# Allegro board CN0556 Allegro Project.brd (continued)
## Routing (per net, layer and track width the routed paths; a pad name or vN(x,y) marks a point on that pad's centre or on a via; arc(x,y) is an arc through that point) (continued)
V1_ADC: length 143.4
  TOP w0.305: U4.4 46.76,34.42 47.24,33.93 47.24,33.2 47.92,32.52 U4.1 v1(48.62,31.62)
  L3_PWR w0.305: v1(48.62,31.62) 49.76,32.77 58.37,32.77 67.23,23.9 119.38,23.9 124.31,28.83 175.97,28.83 ADCCON.19
V1D: length 121.6
  TOP w0.203: U1.36 92.31,54.62 91.87,54.18
  TOP w0.508: 91.87,54.18 89.46,54.18 88.95,54.69 C2.1 v1(86.74,55.68) ; R1.2 83.24,44.53 82.26,43.55 RFB1A.1 82.21,43.23 C1.1 82.21,37.86 v1(82.19,37.85)
  L3_PWR w0.508: v1(38.94,81.91) 38.94,42.16 43.13,37.97 82.07,37.97 v1(82.19,37.85) 84.68,37.85 86.74,39.9 v1(86.74,55.68)
  vias: v1(40.06,88.98) v1(40.31,87.2) v1(40.31,86.31) v1(40.31,85.29) v1(40.31,84.4) v1(40.31,83.52) v1(40.31,82.63) v1(40.44,101.3) v1(40.46,99.39) v1(40.46,96.9) v1(40.44,95.55) v1(40.44,94.28) v1(40.41,93.07) v1(40.39,91.72) v1(40.39,90.4) v1(40.44,88.21) v1(40.56,108.53) v1(40.56,107.77) v1(40.56,106.88) v1(40.56,105.99) v1(40.56,104.98) v1(40.56,104.09) v1(40.56,103.2) v1(40.56,102.31) v1(40.49,98.12) v1(40.82,100.53) v1(40.94,88.98) v1(41.07,96.24) v1(41.05,93.75) v1(41.02,92.41) v1(41,91.01) v1(41.17,98.73) v1(41.1,97.59) v1(41.12,94.89) v1(41.33,108.53) v1(41.33,101.3) v1(41.33,88.21) v1(41.55,106.4) v1(41.55,105.51) v1(41.55,104.62) v1(41.55,103.73) v1(41.55,102.84) v1(41.5,86.61) v1(41.5,85.72) v1(41.5,84.84) v1(41.5,83.95) v1(41.5,83.06) v1(41.66,91.72) v1(41.58,90.32) v1(41.71,100.53) v1(41.73,99.42) v1(41.76,98.12) v1(41.73,96.9) v1(41.71,95.55) v1(41.71,94.28) v1(41.68,93.07) v1(41.83,88.98) v1(42.09,108.53) v1(42.21,101.3) v1(42.27,91.01) v1(42.21,88.21) v1(42.27,87) v1(42.27,86.11) v1(42.27,85.22) v1(42.27,84.33) v1(42.27,83.44) v1(42.32,106.78) v1(42.32,105.89) v1(42.32,105) v1(42.32,104.11) v1(42.32,103.23) v1(42.37,97.56) v1(42.34,96.22) v1(42.34,94.89) v1(42.32,93.73) v1(42.29,92.38) v1(42.39,98.73) v1(42.6,100.53) v1(42.72,88.98) v1(42.85,108.53) v1(42.88,91.72) v1(42.85,90.32) v1(42.98,98.12) v1(42.95,96.9) v1(42.93,95.55) v1(42.93,94.28) v1(42.9,93.07) v1(43,99.42) v1(43.1,101.3) v1(43.1,88.21) v1(43.36,87.2) v1(43.36,86.31) v1(43.36,85.29) v1(43.36,84.4) v1(43.36,83.52) v1(43.36,82.63) v1(43.48,100.53) v1(43.56,96.22) v1(43.56,94.95) v1(43.54,93.73) v1(43.51,92.38) v1(43.48,91.01) v1(43.61,108.53) v1(43.61,107.77) v1(43.61,106.88) v1(43.61,105.99) v1(43.61,104.98) v1(43.61,104.09) v1(43.61,103.2) v1(43.61,102.31) v1(43.61,98.78) v1(43.59,97.56) v1(43.61,88.98) v1(43.99,101.3) v1(44.07,93.09) v1(44.04,91.74) v1(43.99,88.21) v1(44.17,98.15) v1(44.15,96.93) v1(44.12,95.58) v1(44.09,94.31) v1(44.37,100.53) v1(44.5,88.98) v1(44.68,92.43) v1(44.65,91.03) v1(44.75,96.27) v1(44.7,93.78) v1(44.86,98.76) v1(44.78,97.61) v1(44.78,94.92) v1(44.88,101.3) v1(44.88,88.21) v1(45.26,100.53) v1(45.36,94.31) v1(45.34,93.09) v1(45.31,91.74) v1(45.44,98.15) v1(45.42,96.93) v1(45.39,95.58) v1(45.39,88.98) v1(45.77,101.3) v1(45.77,88.21) v1(45.97,93.75) v1(45.95,92.41) v1(45.92,91.03) v1(46.08,98.76) v1(46.05,97.59) v1(46.02,96.24) v1(46,94.92) v1(46.15,100.53) v1(46.28,88.98) v1(46.56,93.09) v1(46.53,91.74) v1(46.66,101.3) v1(46.66,98.15) v1(46.63,96.93) v1(46.61,95.58) v1(46.58,94.31) v1(46.66,88.21) v1(47.04,100.53) v1(47.17,92.41) v1(47.14,91.03) v1(47.17,88.98) v1(47.27,97.59) v1(47.24,96.24) v1(47.22,94.97) v1(47.19,93.75) v1(47.29,98.81) v1(47.55,101.3) v1(47.55,88.21) v1(47.93,100.53) v1(47.93,88.98) v1(48.31,101.3) v1(48.31,88.21) v1(48.69,100.53) v1(50.01,82.98) v1(50.09,85.55) v1(50.32,107.29) v1(50.47,84.79) v1(50.39,82.22) v1(50.6,105.11) v1(50.7,106.53) v1(50.98,104.34) v1(50.98,85.55) v1(50.9,82.98) v1(51.21,107.29) v1(51.36,84.79) v1(51.28,82.22) v1(51.49,105.11) v1(51.59,106.53) v1(51.87,104.34) v1(51.87,85.55) v1(51.79,82.98) v1(52.1,107.29) v1(52.17,82.22) v1(52.25,84.79) v1(52.37,105.11) v1(52.48,106.53) v1(52.76,104.34) v1(52.76,85.55) v1(52.68,82.98) v1(52.98,107.29) v1(53.06,82.22) v1(53.14,84.79) v1(53.26,105.11) v1(53.37,106.53) v1(53.57,82.98) v1(53.64,104.34) v1(53.64,85.55) v1(53.87,107.29) v1(53.95,82.22) v1(54.03,84.79) v1(54.15,105.11) v1(54.25,106.53) v1(54.53,104.34) v1(54.53,85.55) v1(54.91,84.79) v1(55.04,105.11) v1(55.42,104.34) v1(55.42,85.55) v1(55.8,84.79) v1(55.93,105.11) v1(56.16,96.44) v1(56.16,95) v1(56.13,93.57) v1(56.18,97.92) v1(56.31,104.34) v1(56.31,85.55) v1(56.39,82.93) v1(56.57,107.31) v1(56.57,97.16) v1(56.54,95.68) v1(56.54,94.23) v1(56.52,92.81) v1(56.69,84.79) v1(56.77,82.17) v1(56.82,105.11) v1(56.95,106.55) v1(57.07,97.92) v1(57.05,96.44) v1(57.05,95) v1(57.02,93.57) v1(57.2,104.34) v1(57.2,85.55) v1(57.28,82.93) v1(57.45,107.31) v1(57.45,97.16) v1(57.43,95.68) v1(57.43,94.23) v1(57.4,92.81) v1(57.58,84.79) v1(57.66,82.17) v1(57.71,105.11) v1(57.84,106.55) v1(57.96,97.92) v1(57.94,96.44) v1(57.94,95) v1(57.91,93.57) v1(57.96,85.55) v1(58.09,104.34) v1(58.17,82.93) v1(58.34,107.31) v1(58.34,97.16) v1(58.32,95.68) v1(58.32,94.23) v1(58.29,92.81) v1(58.34,84.79) v1(58.47,105.11) v1(58.55,82.17) v1(58.72,106.55) v1(58.85,104.34) v1(58.85,97.92) v1(58.83,96.44) v1(58.83,95) v1(58.8,93.57) v1(59.05,82.93) v1(59.23,107.31) v1(59.23,97.16) v1(59.21,95.68) v1(59.21,94.23) v1(59.18,92.81) v1(59.44,82.17) v1(59.61,106.55) v1(59.74,97.92) v1(59.72,96.44) v1(59.72,95) v1(59.69,93.57) v1(59.94,82.93) v1(60.07,92.81) v1(60.12,107.31) v1(60.12,97.16) v1(60.1,95.68) v1(60.1,94.23) v1(60.33,82.17) v1(60.5,106.55)
V2_ADC: length 131.2
  TOP w0.305: U5.4 56.54,34.42 57.15,33.81 57.15,32.87 57.51,32.52 U5.1 v1(58.4,31.62)
  L3_PWR w0.305: v1(58.4,31.62) 66.73,23.29 119.89,23.29 122.89,26.29 178.51,26.29 ADCCON.23
V2D: length 106.9
  TOP w0.508: R14.1 103.49,42.71 103.44,42.76 ; 103.44,42.76 C6.1 104.68,41.01 v1(104.69,41.02) ; 103.44,42.76 RFB2A.1
  L3_PWR w0.508: v1(104.69,41.02) 106.67,39.04 160.6,39.04 167.72,46.15 v1(167.72,81.91)
  vias: v1(166.52,109.17) v1(166.52,106.63) v1(166.52,104.09) v1(166.52,101.55) v1(166.52,88.85) v1(166.52,86.31) v1(166.52,83.77) v1(166.52,81.23) v1(167.11,98.68) v1(167.13,97.46) v1(167.16,96.11) v1(167.11,94.79) v1(167.18,93.72) v1(167.59,107.95) v1(167.59,105.41) v1(167.59,102.87) v1(167.59,100.33) v1(167.59,90.17) v1(167.59,87.63) v1(167.59,85.09) v1(167.59,82.68) v1(167.72,98.12) v1(167.74,96.77) v1(167.72,95.5) v1(167.84,109.22) v1(167.79,94.18) v1(168.33,98.68) v1(168.35,97.46) v1(168.38,96.11) v1(168.38,94.79) v1(168.45,93.72) v1(168.86,106.68) v1(168.86,104.14) v1(168.86,101.6) v1(168.86,88.9) v1(168.86,86.36) v1(168.86,83.82) v1(168.86,81.91) v1(168.99,109.22) v1(168.99,98.15) v1(169.01,96.8) v1(169.04,95.5) v1(169.06,94.18) v1(170,81.91) v1(170.13,109.22) v1(170.13,107.95) v1(170.13,105.41) v1(170.13,102.87) v1(170.13,100.33) v1(170.13,90.17) v1(170.13,87.63) v1(170.13,85.09) v1(170.13,82.68) v1(170.23,98.15) v1(170.26,96.8) v1(170.28,95.5) v1(170.33,94.18) v1(170.87,98.68) v1(170.89,97.46) v1(170.92,96.11) v1(170.92,94.79) v1(170.92,93.5) v1(170.92,92.08) v1(171.27,81.91) v1(171.4,109.22) v1(171.4,106.68) v1(171.4,104.14) v1(171.4,101.6) v1(171.45,92.78) v1(171.4,91.44) v1(171.4,88.9) v1(171.4,86.36) v1(171.4,83.82) v1(171.5,99.92) v1(171.5,98.02) v1(171.53,96.8) v1(171.55,95.45) v1(171.5,94.13) v1(172.06,92.1) v1(172.09,98.63) v1(172.11,97.46) v1(172.14,96.11) v1(172.11,94.84) v1(172.11,93.45) v1(172.42,81.91) v1(172.54,109.22) v1(172.67,107.95) v1(172.67,105.41) v1(172.67,102.87) v1(172.67,100.33) v1(172.67,90.17) v1(172.67,87.63) v1(172.67,85.09) v1(172.67,82.68) v1(172.72,98.02) v1(172.75,96.8) v1(172.77,95.45) v1(172.77,94.13) v1(172.72,92.78) v1(173.28,92.1) v1(173.3,98.63) v1(173.33,93.45) v1(173.38,97.49) v1(173.41,96.14) v1(173.43,94.84) v1(173.56,81.91) v1(173.69,109.22) v1(173.94,106.68) v1(173.94,104.14) v1(173.94,101.6) v1(173.94,91.44) v1(173.94,88.9) v1(173.94,86.36) v1(173.94,83.82) v1(173.99,98.02) v1(174.02,96.8) v1(174.04,95.45) v1(174.04,94.13) v1(173.99,92.78) v1(174.09,99.72) v1(174.83,81.91) v1(174.96,109.22) v1(175.21,107.95) v1(175.21,105.41) v1(175.21,102.87) v1(175.21,100.33) v1(175.21,97.79) v1(175.21,95.25) v1(175.21,92.71) v1(175.21,90.17) v1(175.21,87.63) v1(175.21,85.09) v1(175.21,82.68) v1(175.97,81.91) v1(176.1,109.22) v1(176.35,99.06) v1(176.35,96.52) v1(176.35,93.98) v1(176.35,91.44) v1(176.48,88.9) v1(176.48,86.36) v1(176.48,83.82) v1(177.11,81.91) v1(177.24,109.22) v1(177.75,107.95) v1(177.75,105.41) v1(177.75,102.87) v1(177.75,100.33) v1(177.75,97.79) v1(177.75,95.25) v1(177.75,92.71) v1(177.75,89.79) v1(177.75,87.63) v1(177.75,85.09) v1(177.75,82.68) v1(178.51,109.22) v1(178.51,81.91) v1(179.02,106.68) v1(179.02,104.14) v1(179.02,101.6) v1(179.02,99.06) v1(179.02,96.52) v1(179.02,93.98) v1(179.02,91.44) v1(179.02,88.9) v1(179.02,86.36) v1(179.02,83.82) v1(179.65,109.22) v1(179.65,81.91) v1(180.29,107.95) v1(180.29,105.41) v1(180.29,102.87) v1(180.29,100.33) v1(180.29,97.79) v1(180.29,95.25) v1(180.29,92.71) v1(180.29,90.17) v1(180.29,87.63) v1(180.29,85.09) v1(180.42,82.68) v1(180.8,109.22) v1(180.8,81.91) v1(181.56,106.68) v1(181.56,104.14) v1(181.56,101.6) v1(181.56,99.06) v1(181.56,96.52) v1(181.56,93.98) v1(181.56,91.44) v1(181.56,88.9) v1(181.56,86.36) v1(181.56,83.82) v1(182.7,82.55) v1(182.83,105.41) v1(182.83,102.87) v1(182.83,100.33) v1(182.83,97.79) v1(182.83,95.25) v1(182.83,92.71) v1(182.83,87.63) v1(182.83,85.09) v1(182.96,89.79) v1(183.72,110.11) v1(183.72,108.97) v1(183.72,107.82) v1(183.72,83.19) v1(183.72,82.04) v1(183.72,80.9) v1(184.1,106.68) v1(184.1,104.14) v1(184.1,101.6) v1(184.1,99.06) v1(184.1,96.52) v1(184.1,93.98) v1(184.1,91.44) v1(184.1,88.9) v1(184.1,86.36) v1(185.37,89.28) v1(185.37,87.63) v1(185.37,85.09) v1(185.5,105.41) v1(185.5,102.87) v1(185.5,100.33) v1(185.5,97.79) v1(185.5,95.25) v1(185.5,93.34)
BG:
  vias: v1(73.61,116.08) v1(73.61,115.32) v1(74.37,116.08) v1(74.37,115.32) v1(79.83,75.31) v1(79.81,74.55) v1(80.59,75.31) v1(80.59,74.55) v1(85.67,116.08) v1(85.67,115.32) v1(86.51,116.08) v1(86.51,115.32) v1(91.9,75.31) v1(91.9,74.55) v1(92.66,75.31) v1(92.66,74.55) v1(99.64,75.31) v1(99.64,74.55) v1(100.41,75.31) v1(100.41,74.55) v1(105.61,64.9) v1(105.61,64.13) v1(106.38,64.9) v1(106.38,64.13)
BIAS: length 45.9
  TOP w0.305: U1.29 95.81,57.73 v1(96.01,57.94) ; R9.1 59.59,42.93 v1(76.63,42.93)
  BOTTOM w0.305: v1(76.63,42.93) 82.12,42.93 96.01,56.82 v1(96.01,57.94)
BOOSTOUT: length 172.9
  TOP w0.508: R2.2 80.72,44.31 v1(80.72,35.31) ; D3.A 97.84,65.31 v1(97.84,66.07) ; R1B.1 v1(52.03,35.51)
  L3_PWR w0.508: v1(97.84,66.07) 97.84,60.93 96.85,59.94 92.51,59.94 90.22,57.66 90.22,50.24 91.69,48.77 91.69,45.16 92.59,44.27 92.59,36.1 91.8,35.31 v1(80.72,35.31) 80.52,35.51 v1(52.03,35.51) 25.53,35.51 20.52,40.51 20.52,88.27 v1(19.71,89.08)
  vias: v1(3.15,93.78) v1(3.15,92.76) v1(3.15,91.74) v1(3.89,94.23) v1(3.89,93.22) v1(3.89,92.2) v1(3.89,91.19) v1(4.5,93.68) v1(5.03,94.36) v1(5.08,92.25) v1(5.46,91.49) v1(5.51,93.68) v1(5.97,92.25) v1(6.05,94.36) v1(6.35,91.49) v1(6.53,93.68) v1(6.86,92.25) v1(7.06,94.36) v1(7.24,91.49) v1(7.54,93.68) v1(7.75,92.25) v1(8.08,94.36) v1(8.13,91.49) v1(8.56,93.68) v1(8.59,109.22) v1(8.64,92.25) v1(8.77,110.6) v1(8.77,107.84) v1(9.02,91.49) v1(9.09,94.36) v1(9.3,111.89) v1(9.3,106.55) v1(9.58,93.68) v1(10.15,112.99) v1(10.15,105.45) v1(10.11,94.36) v1(10.59,93.68) v1(10.59,92.66) v1(10.59,91.64) v1(10.59,90.63) v1(11.25,113.84) v1(11.25,104.6) v1(11.25,94.36) v1(11.35,93.04) v1(11.35,92.02) v1(11.35,91.01) v1(12.54,114.37) v1(12.54,104.07) v1(13.92,114.55) v1(13.92,103.89) v1(15.3,114.37) v1(15.3,104.07) v1(16.59,113.84) v1(16.59,104.6) v1(17.69,112.99) v1(17.69,105.45) v1(18.47,99.77) v1(18.47,98.76) v1(18.47,97.74) v1(18.47,96.72) v1(18.47,95.71) v1(18.47,94.69) v1(18.47,93.68) v1(18.47,92.66) v1(18.47,91.64) v1(18.47,90.63) v1(18.47,89.61) v1(18.54,111.89) v1(18.54,106.55) v1(19.07,110.6) v1(19.07,107.84) v1(19.25,109.22) v1(19.23,99.26) v1(19.23,98.25) v1(19.23,97.23) v1(19.23,96.22) v1(19.23,95.2) v1(19.23,94.18) v1(19.23,93.17) v1(19.23,92.15) v1(19.23,91.14) v1(19.23,90.12) v1(19.74,100.03) v1(20.24,99.39) v1(20.75,100.03) v1(20.7,97.74) v1(20.73,96.52) v1(20.75,95.17) v1(20.78,93.9) v1(20.8,92.68) v1(20.83,91.34) v1(20.85,89.97) v1(21.26,99.39) v1(21.34,97.08) v1(21.36,95.86) v1(21.39,94.51) v1(21.41,93.24) v1(21.44,92.02) v1(21.46,90.68) v1(21.77,100.03) v1(21.92,97.69) v1(21.95,96.52) v1(21.97,95.17) v1(22,93.85) v1(22.02,92.68) v1(22.05,91.34) v1(22.07,89.97) v1(22.28,99.39) v1(22.56,97.08) v1(22.58,95.86) v1(22.61,94.51) v1(22.63,93.24) v1(22.66,92.02) v1(22.68,90.68) v1(22.78,100.03) v1(23.14,97.69) v1(23.22,96.55) v1(23.24,95.2) v1(23.22,93.85) v1(23.29,99.39) v1(23.29,92.71) v1(23.32,91.36) v1(23.34,89.97) v1(23.8,100.03) v1(23.83,97.08) v1(23.85,95.86) v1(23.88,94.51) v1(23.9,93.24) v1(23.93,92.02) v1(23.95,90.68) v1(24.31,99.39) v1(24.38,97.71) v1(24.41,96.49) v1(24.43,95.15) v1(24.43,93.88) v1(24.46,92.66) v1(24.49,91.31) v1(24.51,89.94) v1(24.82,100.03) v1(24.99,98.35) v1(25.02,97.05) v1(25.04,95.83) v1(25.07,94.49) v1(25.07,93.22) v1(25.1,92) v1(25.12,90.65) v1(25.15,89.26) v1(25.32,99.39) v1(25.6,97.66) v1(25.63,96.49) v1(25.65,95.15) v1(25.65,93.83) v1(25.68,92.66) v1(25.7,91.31) v1(25.73,89.94) v1(25.83,100.03) v1(26.26,98.35) v1(26.24,97.05) v1(26.26,95.83) v1(26.34,99.39) v1(26.29,94.49) v1(26.29,93.22) v1(26.31,92) v1(26.34,90.65) v1(26.42,89.26) v1(26.85,100.03) v1(26.82,97.66) v1(26.87,93.83) v1(26.9,96.52) v1(26.92,95.17) v1(26.95,92.68) v1(26.97,91.34) v1(27,89.94) v1(27.36,99.39) v1(27.53,98.32) v1(27.51,97.05) v1(27.53,95.83) v1(27.56,94.49) v1(27.56,93.22) v1(27.58,92) v1(27.61,90.65) v1(27.61,89.33) v1(27.86,100.03) v1(28.37,99.39)
BUCKOUT: length 240.3
  TOP w0.508: R13.1 106.25,42.65 v1(106.25,34.42) ; D2.A v1(102.54,66.01) ; R2B.1 v1(62.69,34.42)
  L3_PWR w0.508: 93.55,34.42 v1(106.25,34.42) 122.99,34.42 123.44,33.96 187.25,33.96 193.65,40.36 193.65,67.92 205.16,79.43 v1(205.16,90.63) ; 93.55,34.42 93.55,48.72 91.82,50.44 91.66,50.44 91.66,57.04 93.27,58.65 100.43,58.65 102.54,60.76 v1(102.54,66.01) ; 93.55,34.42 v1(62.69,34.42)
  vias: v1(204.19,109.14) v1(204.37,110.52) v1(204.37,107.76) v1(204.91,111.81) v1(204.91,106.47) v1(205.16,101.93) v1(205.16,100.91) v1(205.16,99.9) v1(205.16,98.88) v1(205.16,97.87) v1(205.16,96.85) v1(205.16,95.96) v1(205.16,95.07) v1(205.16,94.18) v1(205.16,93.29) v1(205.16,92.41) v1(205.16,91.64) v1(205.75,112.91) v1(205.75,105.37) v1(206.17,101.93) v1(206.17,100.91) v1(206.17,99.9) v1(206.17,98.88) v1(206.17,97.87) v1(206.17,96.85) v1(206.17,95.96) v1(206.17,95.07) v1(206.17,94.18) v1(206.17,93.29) v1(206.17,92.41) v1(206.17,91.64) v1(206.17,90.63) v1(206.86,113.76) v1(206.86,104.52) v1(207.19,101.93) v1(207.19,100.91) v1(207.19,99.9) v1(207.19,98.88) v1(207.19,97.87) v1(207.19,96.85) v1(207.19,95.96) v1(207.19,95.07) v1(207.19,94.18) v1(207.19,93.29) v1(207.34,91.16) v1(207.85,91.92) v1(208.14,114.29) v1(208.14,103.99) v1(208.36,91.16) v1(208.86,91.92) v1(209.37,91.16) v1(209.52,114.47) v1(209.52,103.81) v1(209.88,91.92) v1(210.39,91.16) v1(210.91,114.29) v1(210.91,103.99) v1(210.9,91.92) v1(211.4,91.16) v1(211.91,91.92) v1(212.17,90.65) v1(212.17,89.64) v1(212.17,88.62) v1(212.19,113.76) v1(212.19,104.52) v1(212.8,91.16) v1(212.8,90.14) v1(212.8,89.13) v1(213.3,112.91) v1(213.3,105.37) v1(214.14,111.81) v1(214.14,106.47) v1(214.68,110.52) v1(214.68,107.76) v1(214.86,109.14)
DG1: length 138.9
  TOP w0.508: v1(87.78,58.95) 87.76,58.93 87.1,58.93 86.45,58.28 R3.1
  L3_PWR w0.508: v1(34.24,99.03) v1(33.48,99.03) 32.69,99.03 31.45,97.79 v1(31.45,88.65) v1(32.21,88.65) 34.37,86.49 37.03,86.49 37.92,85.6 37.92,41.66 42.47,37.11 85.39,37.11 87.78,39.5 v1(87.78,58.95)
DG2: length 152.8
  TOP w0.508: v1(189.56,61.8) 135.89,61.8 130.35,67.34 102.72,67.34 v1(102.69,67.31) ; R8.2 v1(90.44,62.55)
  L3_PWR w0.508: v1(102.69,67.31) 97.36,67.31 96.85,66.8 96.85,61.47 96.34,60.96 92.02,60.96 v1(90.44,62.55) ; v1(186.13,91.31) v1(186.89,91.31) 189.56,91.31 ; 189.56,91.31 v1(189.56,61.8) ; 189.56,91.31 189.56,97.54 190.07,98.04 v1(190.07,101.09) v1(189.18,101.09)
DRXN: length 192.3
  TOP w0.203: Q2.1 R24.2
  TOP w0.305: P4.11 194.48,47.47 186.94,47.47 183.85,50.57 182.47,50.57 ADCCON.6 181.07,51.77 178.71,51.77 172.24,58.24 114.37,58.24 112.78,56.64 ; Q2.1 78.73,27.75 82.58,23.9 91.82,23.9 P3.2 96.8,23.85 108.13,23.85 110.44,26.16 110.44,39.55 112.81,41.92 112.81,56.61 112.78,56.64 ; 112.78,56.64 99.61,56.64 99.31,56.34 U1.22
DS1: length 123.3
  TOP w0.305: v1(88.77,58.93) 89.31,58.93 91.81,56.43 U1.37
  L3_PWR w0.508: v1(88.77,58.93) 88.77,38.86 86.26,36.35 41.81,36.35 36.63,41.53 v1(36.63,84.4)
  vias: v1(31.14,100.28) v1(31.65,101.04) v1(32.03,100.28) v1(32.41,101.04) v1(32.79,100.28) v1(33.17,101.04) v1(33.68,100.28) v1(33.93,101.04) v1(34.09,84.4) v1(34.44,100.28) v1(34.47,87.96) v1(34.59,85.17) v1(34.95,101.04) v1(34.98,88.72) v1(34.98,84.4) v1(35.33,100.28) v1(35.36,87.96) v1(35.36,85.17) v1(35.71,101.04) v1(35.74,88.72) v1(35.74,84.4) v1(36.09,100.28) v1(36.12,87.96) v1(36.12,85.17) v1(36.47,101.04) v1(36.5,88.72) v1(36.88,85.17) v1(36.98,100.28) v1(37.01,87.96) v1(37.24,101.04) v1(37.26,88.72)
DS2: length 165.3
  TOP w0.305: U1.34 93.31,56.81 93.07,57.05 v1(93.01,57.05)
  L3_PWR w0.508: v1(190.55,87.96) 190.55,41.53 185.52,36.5 98.2,36.5 95.53,39.17 95.53,48.54 93.01,51.05 v1(93.01,57.05)
  vias: v1(187.63,106.25) v1(187.78,102.62) v1(188.14,105.61) v1(188.14,103.45) v1(188.14,88.34) v1(188.65,106.25) v1(188.67,102.62) v1(189.03,103.45) v1(189.15,105.61) v1(189.79,106.12) v1(189.79,105.11) v1(189.79,104.22) v1(189.79,103.45) v1(189.81,102.62) v1(190.55,105.61) v1(190.55,104.72) v1(190.55,103.84) v1(190.55,102.82) v1(190.68,89.36) v1(191.06,88.6) v1(191.44,89.36) v1(191.57,87.96) v1(191.95,88.6) v1(192.33,89.36) v1(192.46,87.96) v1(192.84,88.6) v1(193.22,89.36) v1(193.34,87.96)
EN: length 274.8
  TOP w0.203: Q1.1 50.28,27.76 50.26,27.77
  TOP w0.305: P4.10 194.48,44.93 187.86,44.93 183.49,49.3 180.99,49.3 ADCCON.5 178.67,50.47 171.5,57.63 114.68,57.63 113.33,56.29 113.33,41.53 111.07,39.27 111.07,25.7 108.69,23.32 81.84,23.32 78.38,26.77 66.14,26.77 61.21,21.84 52.04,21.84 51.13,22.76 51.13,25.68 50.26,26.55 Q1.1 R26.2 50.26,30.15 51.05,30.94 76.66,30.94 77.9,32.18 77.9,61.93 79.17,63.2 90.96,63.2 91.39,62.76 91.39,59.56 93.81,57.14 U1.33
EXTPWR: length 126.3
  TOP w0.635: 125.13,19.99 DACCON.29 ; DACCON.29 126.26,21.12 ; DACCON.29 127.39,19.99 ; ADCCON.29 179.83,21.12 ; ADCCON.29 180.96,19.99 ; ADCCON.29 178.69,19.99
  TOP w1.27: 124.56,19.91 44.55,19.91 41.4,23.06 41.4,45.82 45.49,49.91 P1.1
FAULT: length 222.5
  TOP w0.305: v1(96.93,33.5) 89.41,33.5 86.26,30.35 54.31,30.35 53.19,29.24 53.19,24.84 53.7,24.33 DS2.C ; v1(101.4,57.76) 99.29,57.76 98.31,56.78 U1.24
  BOTTOM w0.305: v1(101.4,57.76) 100.94,57.76 99.62,56.44 99.62,51.18 95,46.56 95,39.62 93.98,38.61 93.98,36.45 v1(96.93,33.5) 100.79,29.64 100.79,24.92 102.95,22.76 113.97,22.76 119.84,28.63 119.84,49.63 124.46,54.25 127.51,54.25 DACCON.2 131.35,55.55 140.18,46.71 193.27,46.71 194.48,47.93 P4.12
FB1: length 93.3
  TOP w0.305: FB1CTL.2 122.39,44.32 122.7,44.02 v1(123.57,44.02) ; v1(84.01,39.82) C1.2 84.01,43.23 RFB1A.2 85.73,43.28 RFB1B.1 85.79,43.24 86.61,44.07 86.82,44.07 90.12,47.37 91.56,47.37 92.81,48.62 U1.4
  BOTTOM w0.305: v1(84.01,39.82) 84.01,28.36 92.99,19.38 116.74,19.38 123.57,26.21 v1(123.57,44.02)
FB1_CTL: length 2.2
  TOP w0.203: DACCON.9 FB1CTL.1
FB2: length 46.9
  TOP w0.305: C6.2 101.69,41.06 RFB2A.2 101.69,43.14 101.49,43.34 RFB2B.1 99.37,46.18 98.55,46.99 v1(98.53,46.99) 98.53,47.02 97.81,47.73 U1.14 ; FB2CTL.2 v1(117.53,42.85)
  BOTTOM w0.305: v1(117.53,42.85) 117.53,38.35 116.41,37.24 103.96,37.24 99.44,41.76 99.44,44.81 98.53,45.72 v1(98.53,46.99)
FB2_CTL: length 2.2
  TOP w0.203: DACCON.11 FB2CTL.1
IMON1: length 139.5
  TOP w0.305: RMON1.1 87.41,43.14 CMON1.1 88.81,43.3 v1(89.74,44.22) 89.74,46.1 90.5,46.86 91.69,46.86 93.27,48.44 93.27,48.5 93.31,48.54 U1.5 ; ADCCON.9 157.7,45.39 151.36,39.04 122.07,39.04 v1(121.21,39.9)
  BOTTOM w0.305: v1(121.21,39.9) 121.21,26.92 115.37,21.08 94.28,21.08 89.74,25.63 v1(89.74,44.22)
IMON2: length 99.4
  TOP w0.305: U1.13 97.31,47.34 98.76,45.9 v1(98.76,44.27) ; CMON2.1 99.32,37.5 RMON2.1 v1(100.9,37.45) ; v1(117.58,37.31) 119.99,37.31 120.8,36.5 152.48,36.5 158.82,42.85 ADCCON.11
  BOTTOM w0.305: v1(117.58,37.31) 116.76,36.5 101.86,36.5 v1(100.9,37.45) 98.76,39.6 v1(98.76,44.27)
INTVCC: length 118.2
  TOP w0.203: CINVCC.1 101.76,54.05
  TOP w0.305: v1(109.8,32.99) 109.8,39.83 112.14,42.16 112.14,53.57 111.38,54.33 CINVCC.1 ; 101.76,54.05 100.13,54.05 99.81,54.37 U1.21 ; v1(115.19,32.99) 116.26,32.99 117.22,33.96 154.2,33.96 160.55,40.31 ADCCON.13
  BOTTOM w0.305: v1(115.19,32.99) v1(109.8,32.99) 105.92,32.99 104.57,31.65 P5.1
ISET1N: length 71.7
  TOP w0.305: v1(88.7,36.3) C1N.1 88.65,37.45 R1N.1 ; RCTL1N.2 122.39,29.48 v1(122.07,29.16) ; v1(90.75,45.97) 91.45,45.97 93.81,48.33 U1.6
  BOTTOM w0.305: v1(90.75,45.97) 89.26,45.97 88.7,45.42 v1(88.7,36.3) 88.7,25.7 93.88,20.52 115.8,20.52 122.07,26.8 v1(122.07,29.16)
ISET1N_CTL: length 2.2
  TOP w0.305: RCTL1N.1 DACCON.21
ISET1P: length 59.2
  TOP w0.305: v1(95.48,35.97) 94.79,36.65 C1P.1 96.27,37.5 R1P.1 ; U1.11 v1(96.31,46.61) ; RCTL1P.2 v1(119.05,32.69)
  BOTTOM w0.305: v1(119.05,32.69) 119.05,28.65 113.69,23.29 103.28,23.29 101.52,25.05 101.52,29.92 v1(95.48,35.97) 94.79,36.65 94.79,38.28 95.86,39.34 95.86,46.16 v1(96.31,46.61)
ISET1P_CTL: length 2.2
  TOP w0.305: RCTL1P.1 DACCON.19
ISET2N: length 61.1
  TOP w0.305: v1(91.74,36.3) C2N.1 91.7,37.45 R2N.1 ; RCTL2N.2 v1(118.34,25.07) ; U1.7 94.31,48.08 92.48,46.25 v1(92.48,45.95)
  BOTTOM w0.305: v1(92.48,45.95) 92.48,40.79 91.74,40.06 v1(91.74,36.3) 91.74,29.51 93.12,28.14 93.12,25.02 96.47,21.67 114.94,21.67 v1(118.34,25.07)
ISET2N_CTL: length 2.2
  TOP w0.305: RCTL2N.1 DACCON.25
ISET2P: length 47.8
  TOP w0.305: U1.12 96.81,47.08 97.82,46.08 v1(97.82,44.81) R2P.1 96.42,43.24 C2P.1 ; RCTL2P.2 v1(115.98,27.61)
  BOTTOM w0.305: v1(97.82,44.81) 97.21,44.2 97.21,39.4 101.27,35.33 114.55,35.33 115.98,33.91 v1(115.98,27.61)
ISET2P_CTL: length 2.2
  TOP w0.305: RCTL2P.1 DACCON.23
PI_5V: length 10.2
  L3_PWR w0.635: ADCCON.30 182.37,21.12 ; ADCCON.30 181.23,19.99 ; ADCCON.30 183.5,19.99 ; 195.44,19.99 P4.1 ; P4.1 196.57,21.12 ; P4.1 197.7,19.99 ; 127.67,19.99 DACCON.30 ; DACCON.30 129.93,19.99 ; DACCON.30 128.8,21.12
  vias: v1(39.93,55.4) v1(39.93,54.64) v1(40.69,55.4) v1(40.69,54.64) v1(70.94,22.61) v1(70.94,21.84) v1(70.94,21.08)
REPORT: length 178.5
  TOP w0.305: U1.25 97.81,56.93 99.25,58.37 v1(105.87,58.37) ; DACCON.1 R23.2
  BOTTOM w0.305: v1(105.87,58.37) 104.37,56.87 100.97,56.87 100.18,56.08 100.18,49.53 96.47,45.82 96.47,38.94 102.13,33.27 102.13,25.32 103.61,23.85 113.41,23.85 118.41,28.85 118.41,49.58 124.38,55.55 DACCON.1 127.46,56.74 131.47,56.74 139.01,49.2 193.22,49.2 194.48,50.47 P4.13
RX: length 58
  BOTTOM w0.305: P2.3 206.48,30.4 206.48,52.86 201.7,57.63 191.36,57.63 186.74,53.01 ADCCON.4
SHARE: length 97.1
  TOP w0.203: R4.1 91.72,26.39 P3.1
  TOP w0.305: ADCCON.15 162.17,37.77 155.83,31.42 v1(117.09,31.42)
  L3_PWR w0.203: v1(117.09,31.42) 96.8,31.42 P3.1
SNS2N: length 3.6
  TOP w0.305: U1.19 101.74,49.63 101.99,49.38 ; RIN2B.2 102.04,49.33 101.99,49.38 ; 101.99,49.38 C4.2
SNS2P: length 5.1
  TOP w0.305: U1.18 99.81,50.5 100.11,50.8 101.71,50.8 101.99,51.08 ; RIN2A.2 102.04,51.13 101.99,51.08 ; 101.99,51.08 C4.1
SYNC: length 187.2
  TOP w0.305: RSYNC.1 108.51,61.47 108.51,58.39 107.7,57.58 v1(103.85,57.58) 102.41,57.58 101.98,57.15 99.34,57.15 98.81,56.62 U1.23
  BOTTOM w0.305: v1(103.85,57.58) 102.94,58.5 100.48,58.5 98.88,56.9 98.88,51.36 95.25,47.73 94.23,47.73 93.37,46.86 93.37,40.41 92.38,39.42 92.38,30.81 P3.3 100.97,22.22 114.38,22.22 120.52,28.37 120.52,49.3 123.06,51.84 133.88,51.84 141.58,44.15 183.36,44.15 185.12,42.39 194.48,42.39 P4.9
T3V3: length 2.2
  TOP w0.508: D5.A P4.3
TX: length 63.1
  BOTTOM w0.305: P2.2 205.84,28.49 205.84,52.55 201.42,56.97 191.54,56.97 186.26,51.69 181.14,51.69 ADCCON.3
UNNAMED_2_ADLT8228_I2_BG: length 13.8
  TOP w0.305: R6.2 106.07,59.89 105.69,59.51 99.1,59.51 96.81,57.22 U1.27
UNNAMED_2_ADLT8228_I2_BST: length 5.7
  TOP w0.305: R5.2 92.4,59.62 94.31,57.71 U1.32
UNNAMED_2_ADLT8228_I2_DG1: length 4.3
  TOP w0.305: U1.38 91.31,56.09 90.04,57.35 R3.2
UNNAMED_2_ADLT8228_I2_DG2: length 7.7
  TOP w0.305: R8.1 88.7,61.38 88.7,60.45 92.81,56.34 U1.35
UNNAMED_2_ADLT8228_I2_DRVCC: length 26.7
  TOP w0.203: DBST.A v1(89.61,65.02)
  TOP w0.305: CDRVCC.1 104.57,60.55 104.15,60.13 99.06,60.13 v1(99.06,60.12) 96.31,57.37 U1.28
  BOTTOM w0.305: v1(99.06,60.12) 99.06,62.59 96.62,65.02 v1(89.61,65.02)
UNNAMED_2_ADLT8228_I2_IGND: length 21.9
  TOP w0.305: v1(101.04,55.43) U1.20 ; P7.1 110.95,44.7 110.65,45 RSHARE.2 v1(111.53,45.72)
  BOTTOM w0.305: v1(111.53,45.72) 103.58,45.72 101.04,48.26 v1(101.04,55.43)
UNNAMED_2_ADLT8228_I2_ISHARE: length 47.3
  TOP w0.203: R4.2 107.35,32.35 v1(107.36,32.34)
  TOP w0.305: U1.17 99.31,48.77 99.82,48.26 v1(100.03,48.26) ; 107.35,32.35 107.26,32.44 v1(107.26,43.43) 108.51,43.43 P6.1
  BOTTOM w0.305: P5.2 107.36,28.01 v1(107.36,32.34) ; v1(100.03,48.26) 104.85,43.43 v1(107.26,43.43)
UNNAMED_2_ADLT8228_I2_RT: length 4.3
  TOP w0.305: U1.16 98.81,48.61 99.86,47.56 RT.1
UNNAMED_2_ADLT8228_I2_SNS1N: length 5.7
  TOP w0.305: U1.2 91.81,50.5 91.45,50.85 90.68,50.85 90.43,50.61 88.96,50.61 88.96,50.6 ; 88.96,50.6 88.96,50.61 RIN1B.2 ; 88.96,50.6 C3.2
UNNAMED_2_ADLT8228_I2_SNS1P: length 4.4
  TOP w0.305: C3.1 88.96,48.81 ; 88.96,48.81 90.01,48.81 90.83,49.63 U1.1 ; 88.96,48.81 RIN1A.2
UNNAMED_2_ADLT8228_I2_SS: length 18.5
  TOP w0.305: U1.9 95.31,47.56 v1(94.34,46.58) ; CSS.1 93.27,36.25 v1(94.34,35.18)
  BOTTOM w0.305: v1(94.34,35.18) 93.24,36.27 93.24,39.04 94.34,40.13 v1(94.34,46.58)
UNNAMED_2_ADLT8228_I2_SW: length 6.1
  TOP w0.305: 94.95,59.05 95.31,58.69 U1.30
  TOP w0.508: v1(95.07,61.85) 95.07,62.5 CBST.1 95.83,62.47 v1(95.83,61.85)
  vias: v1(74.37,113.41) v1(74.37,112.14) v1(74.37,110.87) v1(74.37,109.47) v1(74.37,81.15) v1(74.37,79.76) v1(74.37,78.49) v1(74.37,77.22) v1(75.13,113.92) v1(75.13,112.65) v1(75.13,111.38) v1(75.13,109.98) v1(75.13,80.64) v1(75.13,79.25) v1(75.13,77.98) v1(75.13,76.71) v1(75.77,113.41) v1(75.77,112.01) v1(75.77,110.74) v1(75.77,109.09) v1(75.77,81.41) v1(75.77,79.88) v1(75.77,78.61) v1(75.77,77.22) v1(76.4,113.92) v1(76.4,112.65) v1(76.4,111.38) v1(76.4,109.98) v1(76.4,80.64) v1(76.4,79.25) v1(76.4,77.98) v1(76.4,76.71) v1(77.04,113.41) v1(77.04,112.01) v1(77.04,110.74) v1(77.04,109.09) v1(77.04,81.41) v1(77.04,79.88) v1(77.04,78.61) v1(77.04,77.22) v1(77.67,113.92) v1(77.67,112.65) v1(77.67,111.38) v1(77.67,109.98) v1(77.67,80.64) v1(77.67,79.25) v1(77.67,77.98) v1(77.67,76.71) v1(78.31,113.41) v1(78.31,112.01) v1(78.31,110.74) v1(78.31,109.09) v1(78.31,81.41) v1(78.31,79.88) v1(78.31,78.61) v1(78.31,77.22) v1(78.94,113.92) v1(78.94,112.65) v1(78.94,111.38) v1(78.94,109.98) v1(78.94,80.64) v1(78.94,79.25) v1(78.94,77.98) v1(78.94,76.71) v1(79.83,113.41) v1(79.83,112.14) v1(79.83,110.87) v1(79.83,109.47) v1(79.83,81.15) v1(79.83,79.76) v1(79.83,78.49) v1(79.83,77.22) v1(86.56,113.41) v1(86.56,112.14) v1(86.56,110.87) v1(86.56,109.47) v1(86.56,81.15) v1(86.56,79.76) v1(86.56,78.49) v1(86.56,77.22) v1(87.33,113.92) v1(87.33,112.65) v1(87.33,111.38) v1(87.33,109.98) v1(87.33,80.64) v1(87.33,79.25) v1(87.33,77.98) v1(87.33,76.71) v1(87.96,113.41) v1(87.96,112.01) v1(87.96,110.74) v1(87.96,109.09) v1(87.96,81.41) v1(87.96,79.88) v1(87.96,78.61) v1(87.96,77.22) v1(88.6,113.92) v1(88.6,112.65) v1(88.6,111.38) v1(88.6,109.98) v1(88.6,80.64) v1(88.6,79.25) v1(88.6,77.98) v1(88.6,76.71) v1(89.23,113.41) v1(89.23,112.01) v1(89.23,110.74) v1(89.23,109.09) v1(89.23,81.41) v1(89.23,79.88) v1(89.23,78.61) v1(89.23,77.22) v1(89.87,113.92) v1(89.87,112.65) v1(89.87,111.38) v1(89.87,109.98) v1(89.87,80.64) v1(89.87,79.25) v1(89.87,77.98) v1(89.87,76.71) v1(90.5,113.41) v1(90.5,112.01) v1(90.5,110.74) v1(90.5,109.09) v1(90.5,81.41) v1(90.5,79.88) v1(90.5,78.61) v1(90.5,77.22) v1(91.14,113.92) v1(91.14,112.65) v1(91.14,111.38) v1(91.14,109.98) v1(91.14,80.64) v1(91.14,79.25) v1(91.14,77.98) v1(91.14,76.71) v1(92.02,113.41) v1(92.02,112.14) v1(92.02,110.87) v1(92.02,109.47) v1(92.02,81.15) v1(92.02,79.76) v1(92.02,78.49) v1(92.02,77.22) v1(97.61,95) v1(97.61,94.23) v1(98.37,95) v1(98.37,94.23) v1(112.65,106.65) v1(112.65,105.77) v1(112.65,104.88) v1(112.65,103.99) v1(112.65,103.1) v1(112.65,102.21) v1(112.65,101.32) v1(112.65,100.43) v1(112.65,99.54) v1(112.73,107.7) v1(112.73,98.55) v1(112.98,108.58) v1(113.28,107.16) v1(113.28,106.27) v1(113.28,105.38) v1(113.28,104.5) v1(113.28,103.61) v1(113.28,102.72) v1(113.28,101.83) v1(113.28,100.94) v1(113.28,100.05) v1(113.28,99.16) v1(113.46,108.03) v1(113.49,97.28) v1(113.97,108.79) v1(114.1,97.99) v1(114.35,97.23) v1(114.48,108.15) v1(114.86,108.79) v1(114.99,97.99) v1(115.24,97.23) v1(115.37,108.15) v1(115.75,108.79) v1(115.87,97.99) v1(116.13,97.23) v1(116.26,108.15) v1(116.64,108.79) v1(116.76,97.99) v1(117.02,97.23) v1(117.14,108.15) v1(117.53,108.79) v1(117.65,97.99) v1(117.91,97.23) v1(118.03,108.15) v1(118.57,108.71) v1(118.49,107.16) v1(118.49,106.27) v1(118.49,105.38) v1(118.49,104.5) v1(118.49,103.61) v1(118.49,102.72) v1(118.49,101.83) v1(118.49,100.94) v1(118.49,100.05) v1(118.49,99.16) v1(118.49,98.27) v1(119.13,107.67) v1(119.13,106.78) v1(119.13,105.89) v1(119.13,105) v1(119.13,104.11) v1(119.13,103.23) v1(119.13,102.34) v1(119.13,101.45) v1(119.13,100.56) v1(119.13,99.67) v1(119.13,98.78) v1(119.13,97.89)
UNNAMED_2_ADLT8228_I2_TG: length 5.3
  TOP w0.305: U1.31 94.81,57.97 93.9,58.88 R7.2
UNNAMED_2_ADLT8228_I2_TMR: length 14.4
  TOP w0.305: CTMR.2 107.32,59.75 106.55,58.98 99.21,58.98 97.31,57.08 U1.26
UNNAMED_2_ADLT8228_I2_VC1: length 7.7
  TOP w0.305: U1.8 94.81,47.92 93.09,46.2 93.09,45.68 CC1A.2 92.31,43.64 CC1B.2
UNNAMED_2_ADLT8228_I2_VC2: length 7.5
  TOP w0.305: U1.10 95.81,47.09 94.16,45.44 CC2A.1 94.16,43.97 93.34,43.14 CC2B.1
UNNAMED_2_CAP_I33_N2: length 5.6
  TOP w0.203: CBST.2 94.88,65.02 DBST.C 92.4,63.87 R5.1
UNNAMED_2_CAP_I57_N1: length 1.5
  TOP w0.381: RDG1.2 CDG1.1
UNNAMED_2_CAP_I63_N1: length 1.4
  TOP w0.381: RDG2.2 CDG2.1
UNNAMED_2_CAP_I97_N1: length 1.8
  TOP w0.305: RC1.2 90.71,43.64 CC1A.1
UNNAMED_2_CAP_I106_N2: length 2.6
  TOP w0.305: CC2A.2 96.07,45.04 95.2,44.17 95.2,43.63 RC2.1
UNNAMED_2_CAP_I112_N1: length 4.8
  TOP w0.305: P6.2 108.53,44.7 108.95,45.12 RSHARE.1 108.95,47.33 108.71,47.57 CSHARE.1
UNNAMED_2_CAP_I268_N1:
  vias: v1(65.56,97.89) v1(65.53,96.42) v1(65.53,94.97) v1(65.51,93.55) v1(65.94,97.13) v1(65.91,95.66) v1(65.91,94.21) v1(65.89,92.79) v1(66.45,97.89) v1(66.42,96.42) v1(66.42,94.97) v1(66.4,93.55) v1(66.78,92.79) v1(66.83,97.13) v1(66.8,95.66) v1(66.8,94.21) v1(67.34,97.89) v1(67.31,96.42) v1(67.31,94.97) v1(67.28,93.55) v1(67.67,92.79) v1(67.72,97.13) v1(67.69,95.66) v1(67.69,94.21) v1(68.17,93.55) v1(68.22,97.89) v1(68.2,96.42) v1(68.2,94.97) v1(68.55,92.79) v1(68.61,97.13) v1(68.58,95.66) v1(68.58,94.21) v1(69.06,93.55) v1(69.11,97.89) v1(69.09,96.42) v1(69.09,94.97) v1(69.47,95.66) v1(69.47,94.21) v1(69.44,92.79) v1(69.49,97.13) v1(70.18,102.36) v1(70.18,87.63) v1(70.94,102.36) v1(70.94,87.63) v1(71.7,102.36) v1(71.7,87.63) v1(74.37,104.01) v1(74.37,102.74) v1(74.37,101.35) v1(74.37,100.08) v1(74.37,89.92) v1(74.37,88.52) v1(74.37,87.25) v1(74.37,85.98) v1(75.13,104.52) v1(75.13,103.38) v1(75.13,102.11) v1(75.13,100.71) v1(75.13,89.28) v1(75.13,87.88) v1(75.13,86.61) v1(75.13,85.47) v1(75.77,104.01) v1(75.77,102.74) v1(75.77,101.47) v1(75.77,99.82) v1(75.77,90.17) v1(75.77,88.52) v1(75.77,87.25) v1(75.79,85.95) v1(76.4,104.52) v1(76.4,103.38) v1(76.4,100.71) v1(76.4,89.28) v1(76.4,87.88) v1(76.4,86.61) v1(76.4,85.47) v1(76.53,102.11) v1(77.04,104.01) v1(77.04,102.74) v1(77.04,101.47) v1(77.04,99.82) v1(77.04,90.17) v1(77.04,88.52) v1(77.04,87.25) v1(77.04,85.98) v1(77.55,87.88) v1(77.67,104.52) v1(77.67,103.38) v1(77.67,102.11) v1(77.67,100.71) v1(77.67,89.28) v1(77.67,86.61) v1(77.67,85.47) v1(78.28,104.04) v1(78.31,102.74) v1(78.31,101.47) v1(78.31,99.82) v1(78.31,90.17) v1(78.31,88.52) v1(78.31,87.25) v1(78.31,85.98) v1(78.94,104.52) v1(78.94,103.38) v1(78.94,102.11) v1(78.94,100.71) v1(78.94,89.28) v1(78.94,87.88) v1(78.94,86.61) v1(78.94,85.47) v1(79.83,104.01) v1(79.83,102.74) v1(79.83,101.47) v1(79.83,100.08) v1(79.83,89.92) v1(79.83,88.52) v1(79.83,87.12) v1(79.83,85.85) v1(82.25,87.63) v1(82.5,102.36) v1(83.01,87.63) v1(83.26,102.36) v1(83.9,87.63) v1(84.02,102.36) v1(86.44,104.01) v1(86.44,102.74) v1(86.44,101.35) v1(86.44,100.08) v1(86.56,89.92) v1(86.56,88.52) v1(86.56,87.25) v1(86.56,85.98) v1(87.33,104.52) v1(87.33,103.38) v1(87.33,102.11) v1(87.33,100.71) v1(87.33,89.28) v1(87.33,87.88) v1(87.33,86.61) v1(87.33,85.47) v1(87.96,104.01) v1(87.96,102.74) v1(87.96,101.47) v1(87.96,99.82) v1(87.96,90.17) v1(87.96,88.52) v1(87.96,87.25) v1(87.99,85.95) v1(88.6,104.52) v1(88.6,103.38) v1(88.6,100.71) v1(88.6,89.28) v1(88.6,87.88) v1(88.6,86.61) v1(88.6,85.47) v1(88.72,102.11) v1(89.23,104.01) v1(89.23,102.74) v1(89.23,101.47) v1(89.23,99.82) v1(89.23,90.17) v1(89.23,88.52) v1(89.23,87.25) v1(89.23,85.98) v1(89.74,87.88) v1(89.87,104.52) v1(89.87,103.38) v1(89.87,102.11) v1(89.87,100.71) v1(89.87,89.28) v1(89.87,86.61) v1(89.87,85.47) v1(90.47,104.04) v1(90.5,102.74) v1(90.5,101.47) v1(90.5,99.82) v1(90.5,90.17) v1(90.5,88.52) v1(90.5,87.25) v1(90.5,85.98) v1(91.14,104.52) v1(91.14,103.38) v1(91.14,102.11) v1(91.14,100.71) v1(91.14,89.28) v1(91.14,87.88) v1(91.14,86.61) v1(91.14,85.47) v1(92.02,104.01) v1(92.02,102.74) v1(92.02,101.47) v1(92.02,100.08) v1(92.02,90.17) v1(92.02,88.65) v1(92.02,87.25) v1(92.02,85.98) v1(94.69,87.64) v1(95.2,102.36) v1(95.45,87.64) v1(95.96,102.36)
UNNAMED_2_IND_I7_N2:
  vias: v1(140.35,92.35) v1(140.35,91.47) v1(140.35,90.58) v1(140.35,89.69) v1(140.35,88.8) v1(140.35,87.91) v1(140.35,87.02) v1(140.35,86.13) v1(140.35,85.24) v1(140.43,93.4) v1(140.43,84.25) v1(140.68,94.29) v1(140.98,92.86) v1(140.98,91.97) v1(140.98,91.08) v1(140.98,90.2) v1(140.98,89.31) v1(140.98,88.42) v1(140.98,87.53) v1(140.98,86.64) v1(140.98,85.75) v1(140.98,84.86) v1(141.16,93.73) v1(141.19,82.98) v1(141.67,94.49) v1(141.8,83.69) v1(142.05,82.93) v1(142.18,93.85) v1(142.56,94.49) v1(142.69,83.69) v1(142.94,82.93) v1(143.07,93.85) v1(143.45,94.49) v1(143.57,83.69) v1(143.83,82.93) v1(143.96,93.85) v1(144.34,94.49) v1(144.46,83.69) v1(144.72,82.93) v1(144.84,93.85) v1(145.23,94.49) v1(145.35,83.69) v1(145.61,82.93) v1(145.73,93.85) v1(146.27,94.41) v1(146.19,92.86) v1(146.19,91.97) v1(146.19,91.08) v1(146.19,90.2) v1(146.19,89.31) v1(146.19,88.42) v1(146.19,87.53) v1(146.19,86.64) v1(146.19,85.75) v1(146.19,84.86) v1(146.19,83.97) v1(146.83,93.37) v1(146.83,92.48) v1(146.83,91.59) v1(146.83,90.7) v1(146.83,89.81) v1(146.83,88.93) v1(146.83,88.04) v1(146.83,87.15) v1(146.83,86.26) v1(146.83,85.37) v1(146.83,84.48) v1(146.83,83.59) v1(149.81,113.03) v1(149.81,110.49) v1(149.81,107.95) v1(149.81,105.41) v1(149.81,102.87) v1(149.81,100.33) v1(149.81,97.79) v1(149.81,95.25) v1(149.81,92.71) v1(149.81,90.17) v1(149.81,87.63) v1(149.81,85.09) v1(149.81,82.55) v1(149.81,80.01) v1(149.81,77.47) v1(151.08,111.76) v1(151.08,109.22) v1(151.08,106.68) v1(151.08,104.14) v1(151.08,101.6) v1(151.08,99.06) v1(151.08,96.52) v1(151.08,93.98) v1(151.08,91.44) v1(151.08,88.9) v1(151.08,86.36) v1(151.08,83.82) v1(151.08,81.28) v1(151.08,78.74) v1(152.35,113.03) v1(152.35,110.49) v1(152.35,107.95) v1(152.35,105.41) v1(152.35,102.87) v1(152.35,100.33) v1(152.35,97.79) v1(152.35,95.25) v1(152.35,92.71) v1(152.35,90.17) v1(152.35,87.63) v1(152.35,85.09) v1(152.35,82.55) v1(152.35,80.01) v1(152.35,77.47) v1(153.62,111.76) v1(153.62,109.22) v1(153.62,106.68) v1(153.62,104.14) v1(153.62,101.6) v1(153.62,88.9) v1(153.62,86.36) v1(153.62,83.82) v1(153.62,81.28) v1(153.62,78.74) v1(153.87,96.8) v1(153.85,95.45) v1(153.85,94.13) v1(153.9,98.02) v1(154.46,94.84) v1(154.51,97.49) v1(154.48,96.14) v1(154.58,98.63) v1(154.64,93.52) v1(154.89,113.03) v1(154.89,110.49) v1(154.89,107.95) v1(154.89,105.41) v1(154.89,102.87) v1(154.89,100.33) v1(154.89,90.17) v1(154.89,87.63) v1(154.89,85.09) v1(154.89,82.55) v1(154.89,80.01) v1(154.89,77.47) v1(155.17,98.02) v1(155.14,96.8) v1(155.12,95.45) v1(155.12,94.13) v1(155.78,97.46) v1(155.75,96.11) v1(155.78,94.84) v1(155.8,98.63) v1(155.85,93.52) v1(156.16,111.76) v1(156.16,109.22) v1(156.16,106.68) v1(156.16,104.14) v1(156.16,101.6) v1(156.16,88.9) v1(156.16,86.36) v1(156.16,83.82) v1(156.16,81.28) v1(156.16,78.74) v1(156.36,96.8) v1(156.34,95.45) v1(156.39,98.02) v1(156.39,94.13) v1(156.97,96.11) v1(156.97,94.79) v1(157.02,98.68) v1(157,97.46) v1(157.07,93.57) v1(157.43,113.03) v1(157.43,110.49) v1(157.43,107.95) v1(157.43,105.41) v1(157.43,102.87) v1(157.43,100.33) v1(157.43,90.17) v1(157.43,87.63) v1(157.43,85.09) v1(157.43,82.55) v1(157.43,80.01) v1(157.43,77.47) v1(157.56,94.18) v1(157.66,98.15) v1(157.63,96.8) v1(157.61,95.5) v1(158.27,97.46) v1(158.24,96.11) v1(158.24,94.79) v1(158.29,98.68) v1(158.34,93.57) v1(158.7,111.76) v1(158.7,109.22) v1(158.7,106.68) v1(158.7,104.14) v1(158.7,101.6) v1(158.7,88.9) v1(158.7,86.36) v1(158.7,83.82) v1(158.7,81.28) v1(158.7,78.74) v1(159.46,96.16) v1(159.46,94.84) v1(159.38,93.77) v1(159.51,98.73) v1(159.49,97.51) v1(159.97,113.03) v1(159.97,110.49) v1(159.97,107.95) v1(159.97,105.41) v1(159.97,102.87) v1(159.97,100.33) v1(159.97,90.17) v1(159.97,87.63) v1(159.97,85.09) v1(159.97,82.55) v1(159.97,80.01) v1(159.97,77.47) v1(160.05,94.23) v1(160.12,98.17) v1(160.1,96.82) v1(160.12,95.55) v1(160.66,93.77) v1(160.71,97.51) v1(160.68,96.16) v1(160.73,94.84) v1(161.24,111.76) v1(161.24,109.22) v1(161.24,106.68) v1(161.24,104.14) v1(161.24,101.6) v1(161.24,88.9) v1(161.24,86.36) v1(161.24,83.82) v1(161.24,81.28) v1(161.24,78.74)
UNNAMED_2_RES_I42_N1: length 1
  TOP w0.508: v1(94.06,62.99) 94.06,62.17 R7.1
  vias: v1(73.48,106.81) v1(73.48,106.05) v1(74.32,106.81) v1(74.32,106.05) v1(79.71,84.07) v1(79.71,83.24) v1(80.47,84.07) v1(80.47,83.24) v1(85.73,106.8) v1(85.73,106.04) v1(86.51,106.81) v1(86.51,106.05) v1(91.96,84.09) v1(91.95,83.31) v1(92.79,84.07) v1(92.79,83.31) v1(93.29,63.75) v1(93.29,62.99) v1(94.06,63.75)
UNNAMED_2_RES_I147_N1: length 89.7
  TOP w0.279: RIN2A.1 105.9,50.66 v1(106.44,50.66)
  L3_PWR w0.279: v1(163.42,92.02) 164.06,91.39 164.06,69.22 159.79,64.95 122.05,64.95 107.57,50.47 107.09,50.47 106.9,50.66 v1(106.44,50.66)
UNNAMED_2_RES_I148_N1: length 90.5
  TOP w0.279: v1(106.41,49.85) 105.94,49.85 RIN2B.1
  L3_PWR w0.279: v1(106.41,49.85) 106.82,49.85 106.98,50.01 107.76,50.01 122.24,64.49 159.98,64.49 164.52,69.03 164.52,91.39 v1(165.15,92.02)
UNNAMED_2_RES_I149_N1: length 55.1
  TOP w0.279: RIN1A.1 85.12,49.3 84.69,49.3 v1(84.66,49.33)
  TOP w0.305: v1(62.43,91.75) RSNS1.4
  L3_PWR w0.279: v1(62.43,91.75) 62.43,91.44 62.61,91.26 62.61,69.56 82.67,49.5 83.74,49.5 83.92,49.33 v1(84.66,49.33)
UNNAMED_2_RES_I150_N1: length 54.3
  TOP w0.279: v1(84.63,50.19) 85.2,50.19 RIN1B.1
  TOP w0.305: v1(63.2,91.75) RSNS1.3
  L3_PWR w0.279: v1(84.63,50.19) 83.9,50.19 83.67,49.96 82.85,49.96 63.07,69.75 63.07,91.32 63.2,91.44 v1(63.2,91.75)
UNNAMED_2_RES_I264_N1: length 3.1
  TOP w0.305: RUV1A.1 R1.1 R2.1
UNNAMED_2_RES_I266_N2: length 2.8
  TOP w0.305: R13.2 R14.2 RUV2A.1
UNNAMED_3_ADLT3010_I70_ADJ: length 4.4
  TOP w0.381: R11.1 R10.2 49.87,40.41 U2.2
UNNAMED_3_ADLT3010_I70_IN: length 8.2
  TOP w0.381: U2.5 57.49,39.11 57.87,39.49 57.87,41.06 ; 57.87,41.06 U2.8 ; 57.87,41.06 57.87,42.95 R9.2 56.36,42.97 C5.1
UNNAMED_3_ADLT3010_I70_OUT1: length 10.7
  TOP w0.381: C7.1 R10.1 49.84,41.06 U2.1 51.95,41.91
  TOP w0.762: 51.95,41.91 P1.3
UNNAMED_3_CAP_I84_N2: length 14.9
  TOP w0.203: U3.3 45.47,55.48 v1(45.47,60.88)
  L3_PWR w0.203: v1(54.32,59.46) 52.9,60.88 v1(45.47,60.88)
UNNAMED_4_AD8677_I30_: length 3.3
  TOP w0.508: R1A.1 50.43,34.32 R1B.2 U4.3
UNNAMED_4_DIOLED_I3_N: length 2.7
  TOP w0.203: DS3.C Q2.3
UNNAMED_4_DIOLED_I3_P: length 4.1
  TOP w0.203: R27.2 57.82,25.57 58.5,24.89 DS3.A
UNNAMED_4_DIOLED_I6_P: length 2.5
  TOP w0.203: R25.2 DS2.A
UNNAMED_4_DIOLED_I17_N: length 2.7
  TOP w0.203: DS1.C Q1.3
UNNAMED_4_DIOLED_I17_P: length 4
  TOP w0.203: R22.2 47.91,25.57 48.62,24.86 DS1.A
UNNAMED_4_RES_I25_N2: length 3.3
  TOP w0.508: R2A.1 60.21,34.32 R2B.2 U5.3
UV1: length 88
  TOP w0.305: v1(122.81,41.55) 122.39,41.14 UV1CTL.1 ; v1(84.79,44.37) RUV1A.2 84.79,46.02 84.99,46.23 86.18,46.23 86.39,46.43 RUV1B.1 86.6,47.03 87.45,47.88 91.42,47.88 92.31,48.77 U1.3
  BOTTOM w0.305: v1(84.79,44.37) 84.79,28.63 93.45,19.96 116.26,19.96 122.81,26.52 v1(122.81,41.55)
UV1_CTL: length 2.2
  TOP w0.203: DACCON.13 UV1CTL.2
UV2: length 35.7
  TOP w0.305: 101.69,45.85 100.58,45.85 v1(100.14,46.29) 98.31,48.12 U1.15 ; 101.69,45.85 RUV2B.1 ; 101.69,45.85 RUV2A.2 ; v1(116.1,38.05) 122.11,38.05 UV2CTL.2
  BOTTOM w0.305: v1(116.1,38.05) 104.11,38.05 100.14,42.02 v1(100.14,46.29)
UV2_CTL: length 2.2
  TOP w0.203: DACCON.15 UV2CTL.1

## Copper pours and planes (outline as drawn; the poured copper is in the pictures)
3V3 on BOTTOM: 57.48,31.98 57.48,51.44 53.42,51.44 53.42,36.96 45.67,36.96 45.67,27.81 59.16,27.81 62.28,24.69 72.87,24.69 72.87,26.39 63.07,26.39
12V on TOP: 72.97,68.33 100.28,68.33 100.91,67.69 100.91,64.52 99.26,64.52 99.26,66.42 77.04,66.42 72.59,61.98 65.61,61.98 63.7,63.88 56.08,63.88 56.08,62.1 55.07,62.1 55.07,67.56 72.21,67.56
AGND on TOP: 93.42,53.9 98.2,53.9 98.2,53.34 104.29,53.34 104.29,52.12 98.2,52.12 98.2,51.16 93.42,51.16
AGND on TOP: 1.27,133.35 222.2,133.35 222.2,1.27 194.87,1.27 121.69,1.27 1.27,1.27 ; 29 cut-outs
AGND on BOTTOM: 1.27,133.35 222.2,133.35 222.2,1.27 1.27,1.27 ; 11 cut-outs
AGND on L2_GND: 1.27,133.35 222.2,133.35 222.2,1.27 1.27,1.27 ; 3 cut-outs
AGND on L3_PWR: 1.27,133.35 222.2,133.35 222.2,1.27 194.87,1.27 121.69,1.27 1.27,1.27 ; 4 cut-outs
V1D on TOP: 38.28,109.04 38.28,81.48 62.18,81.48 62.18,109.04
V1D on BOTTOM: 38.28,109.04 38.28,81.48 60.78,81.48 60.78,109.04
V2D on TOP: 165,111.46 165,79.71 185.85,79.71 185.85,111.46
V2D on BOTTOM: 166.29,111.46 166.29,79.71 185.85,79.71 185.85,111.46
BG on TOP: 78.69,75.69 78.69,74.17 80.98,74.17 80.98,75.69
BG on TOP: 85.29,116.46 85.29,114.94 87.58,114.94 87.58,116.46
BG on TOP: 105.49,65.28 106.63,65.28 106.88,65.02 106.88,64.01 106.63,63.75 106.63,63.12 105.49,63.12 105.49,63.75 105.23,64.01 105.23,65.02
BG on TOP: 73.1,116.46 73.1,114.94 75.39,114.94 75.39,116.46
BG on TOP: 91.01,75.69 91.01,74.17 100.66,74.17 100.66,75.69
BG on L3_PWR: 73.56,116.26 100.79,116.26 100.79,75.82 101.19,75.41 106.63,75.41 106.63,63.75 105.49,63.75 105.49,73.79 105.03,74.24 99.39,74.24 99.39,114.22 98.5,115.11 73.56,115.11
BG on L3_PWR: 79.38,75.69 79.38,74.17 92.71,74.17 92.96,74.42 92.96,75.39 92.66,75.69
BIAS on TOP: 102.82,61.32 100.08,61.32 96.11,57.35 95.73,57.35 95.73,58.45 96.75,59.46 96.75,63.45 96.77,63.47 102.82,63.47
BOOSTOUT on TOP, BOTTOM: 2.72,124.28 2.72,88.72 29.9,88.72 29.9,124.28
BUCKOUT on TOP, BOTTOM: 195.71,124.41 195.71,85.32 220.27,85.32 220.27,124.41
DG1 on TOP: 37.54,98.5 37.54,99.31 33.22,99.31 33.22,98.76 34.06,98.76 34.06,98.5
DG1 on TOP: 28.27,87.5 28.27,85.72 32.84,85.72 32.84,88.65 33.6,88.65 33.6,89.92 30.81,89.92 30.81,87.5
DG2 on TOP: 191.72,106.96 194.08,106.96 194.08,100.71 188.8,100.71 188.8,101.6 191.72,101.6
DG2 on TOP: 190.2,90.8 190.2,91.69 185.88,91.69 185.88,90.8
DS1 on TOP: 30.78,109.04 30.78,90.3 33.86,90.3 33.86,87.88 33.6,87.88 33.6,81.41 37.64,81.41 37.64,109.04
DS1 on BOTTOM: 30.78,109.04 30.78,90.3 33.6,90.3 33.6,81.41 37.64,81.41 37.64,109.04
DS2 on TOP, BOTTOM: 187.05,106.96 187.05,79.71 194.08,79.71 194.08,106.96
EXTPWR on TOP: 193.9,19.08 193.9,25.37 192.99,25.37 192.46,24.84 192.46,24.61 191.8,23.95 125.04,23.95 124.36,23.27 124.36,21.34 123.62,20.6 123.62,19.3 123.85,19.08
PI_5V on TOP: 37.92,65.53 37.92,53.21 43.89,53.21 43.89,65.53
PI_5V on BOTTOM: 39.29,56.01 41.07,56.01 41.07,22.86 72.09,22.86 72.09,20.88 39.29,20.88
PI_5V on L3_PWR: 70.05,23.55 70.05,19.08 198.09,19.08 198.09,23.55
UNNAMED_2_ADLT8228_I2_SW on TOP: 95.33,58.55 96.16,59.39 96.16,62.41 95.96,62.61 95.05,62.61 94.82,62.38 94.82,59.05
UNNAMED_2_ADLT8228_I2_SW on TOP: 73.99,114.17 126.54,114.17 126.54,76.4 74.07,76.4 74.07,84.2 77.95,84.2 77.95,81.99 81.05,81.99 81.05,81.03 85.22,81.03 85.22,84.2 90.17,84.2 90.17,82.12 93.55,82.12 93.55,81.03 97.28,81.03 97.28,109.02 93.22,109.02 93.22,105.79 88.29,105.79 88.29,107.7 85.09,107.7 85.09,109.02 81.08,109.02 81.08,105.87 76.15,105.87 76.15,107.7 73.99,107.7
UNNAMED_2_ADLT8228_I2_SW on BOTTOM: 74.12,114.17 126.54,114.17 126.54,76.4 74.07,76.4 74.07,84.2 77.95,84.2 77.95,81.99 81.05,81.99 81.05,81.03 85.22,81.03 85.22,84.2 90.17,84.2 90.17,82.12 93.27,82.12 93.27,81.03 97.28,81.03 97.28,109.02 93.22,109.02 93.22,105.79 88.29,105.79 88.29,107.7 85.09,107.7 85.09,109.02 81.08,109.02 81.08,105.87 76.15,105.87 76.15,107.7 74.12,107.7
UNNAMED_2_ADLT8228_I2_SW on L3_PWR: 97.28,95.38 98.76,95.38 98.76,74.83 98.17,74.24 96.37,74.24 96.11,73.99 96.11,61.59 94.82,61.59 94.82,75.08 95.17,75.44 97.03,75.44 97.28,75.69
UNNAMED_2_CAP_I268_N1 on TOP: 63.45,85.14 96.34,85.14 96.34,104.8 63.45,104.8
UNNAMED_2_CAP_I268_N1 on BOTTOM: 64.95,85.14 96.34,85.14 96.34,104.8 64.95,104.8
UNNAMED_2_CAP_I276_N1 on TOP: 4.37,87.58 4.37,78.94 9.7,78.94 9.7,87.58
UNNAMED_2_CAP_I281_N1 on TOP: 206.93,87.07 206.93,78.31 212.52,78.31 212.52,87.07
UNNAMED_2_IND_I7_N2 on TOP: 137.46,114.17 137.46,76.4 163.53,76.4 163.53,114.17
UNNAMED_2_IND_I7_N2 on BOTTOM: 137.46,114.17 137.46,76.4 162.26,76.4 162.26,114.17
UNNAMED_2_RES_I42_N1 on TOP: 94.18,64.13 93.29,64.13 93.04,63.88 93.04,62.74 93.42,62.36 93.42,61.59 94.18,61.59 94.18,62.61 94.44,62.87 94.44,63.88
UNNAMED_2_RES_I42_N1 on TOP: 78.74,84.45 78.74,82.8 80.85,82.8 80.85,84.45
UNNAMED_2_RES_I42_N1 on TOP: 90.93,84.45 90.93,82.93 93.17,82.93 93.17,84.45
UNNAMED_2_RES_I42_N1 on TOP: 85.29,107.19 85.29,105.66 87.63,105.66 87.63,107.19
UNNAMED_2_RES_I42_N1 on TOP: 73.1,107.19 73.1,105.66 75.44,105.66 75.44,107.19
UNNAMED_2_RES_I42_N1 on L3_PWR: 73.61,106.93 94.41,106.93 94.56,106.78 94.56,62.36 93.04,62.36 93.04,82.93 79.38,82.93 79.38,84.33 93.04,84.33 93.27,84.56 93.27,105.49 92.96,105.79 73.61,105.79
UNNAMED_3_CAP_I84_N2 on TOP: 56.85,63.12 57.89,63.12 57.89,59.05 54.08,59.05 54.08,61.21 56.85,61.21
UNNAMED_3_DIOSCHOTTKY_I90_P on TOP: 52.65,63.75 52.65,65.79 47.57,65.79 47.57,58.06 48.01,57.63 48.01,54.46 47.4,53.85 44.65,53.85 44.65,53.21 49.48,53.21 51,54.74 51,62.99 51.77,63.75

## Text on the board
User.Comments: 5.    INSTALL STANDOFF ON SECONDARY SIDE(M032310) AND SCREW(M000103) ON PRIMARY SIDE.
Ref Des/Assembly Top: A | C | +
Ref Des/Silkscreen Top: HOT SURFACE | WARNING: | A | C | SHARE | DRXN | SYNC | AGND | POWER CONTOL BOARD | +
PAGE_OUTLINE: 26MAR21 | B | C | C1 | CHANGES AS PER ECR-106954 | CHANGES AS PER ECR-115516 | CHANGES AS PER ECR-116503 | 30MAY23 | 10AUG23 | 16AUG23 | A.CATAPANG | A.OESMER | CUSTOMER EVAL Z
DIMENSION: DIA MAX | DIA MAX/SEE NOTE 15 | - | " " | (REF) | +/- 5MILS
User.17: 08-      -07 | L2 GND
User.18: 08-      -08 | L3 PWR
User.45: DETAIL A | 3 PLACES | DETAIL B | SEE NOTE 5 | (6 PLACES) | (4 PLACES) | FIGURE | SIZE | 10.0 | 10.01 | 45.0 | 100.0 | 213.0 | 135.0 | 315.0x120.0 | PLATED | NON-PLATED | DRILL CHART: TOP to BOTTOM | ALL UNITS ARE IN MILS | QTY | 2044 | 484 | 98 | 2 | 4 | 6 | TOLERANCE/NOTES
